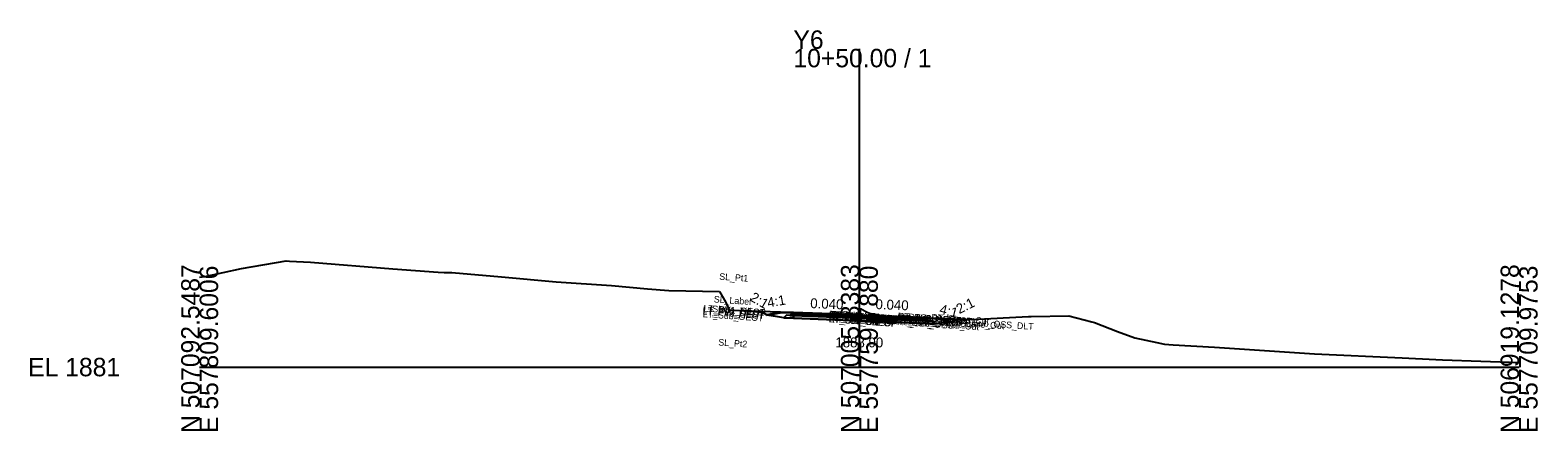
# Model space of a CAD drawing. Extents: x -26 to 203, y -10 to 1539.
# Drawn here: x -25.7 to 202.8, y 490.3 to 551.2 of the extents above; entities that cross this region are included whole.
import ezdxf

# ---------------------------------------------------------------- set-up
doc = ezdxf.new("R2010")
doc.units = 0
for name, color, linetype in [('Default', 7, 'Continuous'), ('Exist Cross Section Cell', 7, 'Continuous'), ('Exist XS Center Line Elevation Label', 7, 'Continuous'), ('Exist XS Ground Line', 7, 'Continuous'), ('Prop CMT Pvmt Course 1', 7, 'Continuous'), ('Prop CMT Pvmt Course 2', 7, 'Continuous'), ('Prop CMT Pvmt Course 3', 7, 'Continuous'), ('Prop CMT Pvmt Surface', 7, 'Continuous'), ('Prop CMT Pvmt Surface Shoulder', 7, 'Continuous'), ('Prop CMT Shld Paved Course 1', 7, 'Continuous'), ('Prop CMT Shld Paved Course 2', 7, 'Continuous'), ('Prop CMT Shld Paved Course 3', 7, 'Continuous'), ('Prop CMT Slope Grass', 7, 'Continuous'), ('Prop CMT Subgrade Earthwork', 7, 'Continuous'), ('Prop XS Earthwork Shape', 7, 'Continuous'), ('Prop XS SE Text', 7, 'Continuous'), ('Prop XS Side Slope Text', 7, 'Continuous'), ('Raster_Level_1', 7, 'Continuous'), ('Typical Text Asphalt at Bridge Approach CELL', 7, 'Continuous')]:
    doc.layers.add(name, color=color, linetype=linetype)

msp = doc.modelspace()

# ---------------------------------------------------------------- linework, layer by layer
at = {"layer": 'Exist Cross Section Cell'}
for p, q in [((100, 500), (100, 548.32)), ((0, 500), (100, 500)), ((100, 500), (200, 500))]:
    msp.add_line(p, q, dxfattribs=at)
at = {"layer": 'Exist XS Ground Line'}
for p, q in [((0.76, 513.74), (6.35, 514.96)), ((6.35, 514.96), (13.12, 516.11)), ((13.12, 516.11), (13.64, 516.08)), ((13.64, 516.08), (16.8, 515.93)), ((16.8, 515.93), (29.3, 514.91)), ((29.3, 514.91), (36.13, 514.4)), ((36.13, 514.4), (37.05, 514.38)), ((37.05, 514.38), (37.88, 514.37)), ((37.88, 514.37), (38.23, 514.36)), ((38.23, 514.36), (45.76, 513.7)), ((0, 513.66), (0.76, 513.74)), ((45.76, 513.7), (54.04, 512.94)), ((54.04, 512.94), (62.43, 512.4)), ((62.43, 512.4), (67.89, 511.87)), ((67.89, 511.87), (71.12, 511.64)), ((71.12, 511.64), (78.82, 511.45)), ((78.82, 511.45), (79.75, 509.78)), ((79.75, 509.78), (80.27, 508.66)), ((80.27, 508.66), (88.06, 508.41)), ((88.06, 508.41), (94.39, 508.12)), ((94.39, 508.12), (95.34, 508.08)), ((95.34, 508.08), (98.2, 507.97)), ((98.2, 507.97), (100, 507.9)), ((100, 507.9), (106.74, 507.64)), ((106.74, 507.64), (108.1, 507.56)), ((108.1, 507.56), (111.33, 507.43)), ((111.33, 507.43), (117.07, 507.2)), ((117.07, 507.2), (125.64, 507.66)), ((125.64, 507.66), (126.04, 507.69)), ((126.04, 507.69), (131.76, 507.79)), ((131.76, 507.79), (135.22, 506.89)), ((135.22, 506.89), (135.62, 506.77)), ((135.62, 506.77), (139.13, 505.39)), ((139.13, 505.39), (141.73, 504.46)), ((141.73, 504.46), (145.08, 503.75)), ((145.08, 503.75), (146.27, 503.5)), ((146.27, 503.5), (147.54, 503.36)), ((147.54, 503.36), (153.82, 503.03)), ((153.82, 503.03), (165.97, 502.2)), ((165.97, 502.2), (168.99, 502.03)), ((168.99, 502.03), (182.26, 501.42)), ((182.26, 501.42), (187.39, 501.16)), ((187.39, 501.16), (188.38, 501.11)), ((188.38, 501.11), (200, 500.69))]:
    msp.add_line(p, q, dxfattribs=at)
at = {"layer": 'Prop CMT Pvmt Course 1'}
for points in [[(90, 508.31), (90, 508.06)], [(100, 507.91), (90, 508.31)], [(90, 508.06), (100, 507.66)], [(100, 507.66), (100, 507.91)], [(100, 507.91), (110, 507.51)], [(100, 507.66), (100, 507.91)], [(110, 507.26), (100, 507.66)], [(110, 507.51), (110, 507.26)]]:
    msp.add_lwpolyline(points, dxfattribs=at)
msp.add_lwpolyline([(100, 507.66), (100, 507.79), (100, 507.79), (100, 507.66)], close=True, dxfattribs=at)
msp.add_lwpolyline([(100, 507.66), (100, 507.79), (100, 507.79), (100, 507.66)], close=True, dxfattribs=at)
at = {"layer": 'Prop CMT Pvmt Course 2'}
for points in [[(90, 508.06), (90, 507.81)], [(100, 507.66), (90, 508.06)], [(90, 507.81), (100, 507.41)], [(100, 507.41), (100, 507.66)], [(100, 507.41), (100, 507.66)], [(100, 507.66), (110, 507.26)], [(110, 507.01), (100, 507.41)], [(110, 507.26), (110, 507.01)]]:
    msp.add_lwpolyline(points, dxfattribs=at)
at = {"layer": 'Prop CMT Pvmt Course 3'}
for points in [[(90, 507.81), (90, 507.43)], [(100, 507.41), (90, 507.81)], [(90, 507.43), (100, 507.03)], [(100, 507.03), (100, 507.41)], [(100, 507.41), (110, 507.01)], [(100, 507.03), (100, 507.41)], [(110, 506.64), (100, 507.03)], [(110, 507.01), (110, 506.64)]]:
    msp.add_lwpolyline(points, dxfattribs=at)
at = {"layer": 'Prop CMT Pvmt Surface'}
for points in [[(100, 507.91), (90, 508.31)], [(100, 507.91), (110, 507.51)]]:
    msp.add_lwpolyline(points, dxfattribs=at)
at = {"layer": 'Prop CMT Pvmt Surface Shoulder'}
for points in [[(90, 508.31), (90, 508.31)], [(110, 507.51), (110, 507.51)]]:
    msp.add_lwpolyline(points, dxfattribs=at)
at = {"layer": 'Prop CMT Shld Paved Course 1'}
for points in [[(90, 508.31), (89.73, 508.07)], [(89.73, 508.07), (90, 508.06)], [(90, 508.31), (90, 508.31)], [(90, 508.06), (90, 508.31)], [(110, 507.51), (110, 507.51)], [(110, 507.51), (110.26, 507.25)], [(110, 507.26), (110, 507.51)], [(110.26, 507.25), (110, 507.26)]]:
    msp.add_lwpolyline(points, dxfattribs=at)
at = {"layer": 'Prop CMT Shld Paved Course 2'}
for points in [[(90, 508.06), (89.73, 508.07), (89.46, 507.84)], [(89.46, 507.84), (90, 507.81)], [(90, 507.81), (90, 508.06)], [(110, 507.26), (110.26, 507.25), (110.51, 507)], [(110, 507.01), (110, 507.26)], [(110.51, 507), (110, 507.01)]]:
    msp.add_lwpolyline(points, dxfattribs=at)
at = {"layer": 'Prop CMT Shld Paved Course 3'}
for points in [[(90, 507.81), (89.46, 507.84), (88.96, 507.86), (88.55, 507.5)], [(88.55, 507.5), (90, 507.43)], [(90, 507.43), (90, 507.81)], [(110, 507.01), (110.51, 507), (111.01, 506.99), (111.39, 506.61)], [(110, 506.64), (110, 507.01)], [(111.39, 506.61), (110, 506.64)]]:
    msp.add_lwpolyline(points, dxfattribs=at)
at = {"layer": 'Prop CMT Slope Grass'}
for points in [[(90, 508.31), (87.99, 508.29), (85.96, 507.92), (84.96, 508.51)], [(110, 507.51), (112, 507.35), (114, 506.85), (114.88, 507.29)]]:
    msp.add_lwpolyline(points, dxfattribs=at)
at = {"layer": 'Prop CMT Subgrade Earthwork'}
for p, q in [((88.55, 507.5), (85.96, 507.92)), ((111.39, 506.61), (114, 506.85))]:
    msp.add_line(p, q, dxfattribs=at)
for points in [[(80.49, 508.65), (80.5, 508.65)], [(90, 507.43), (88.55, 507.5)], [(100, 507.03), (90, 507.43)], [(100, 507.03), (110, 506.64)], [(110, 506.64), (111.39, 506.61)]]:
    msp.add_lwpolyline(points, dxfattribs=at)
at = {"layer": 'Prop XS Earthwork Shape'}
for points in [[(84.88, 508.51), (88.06, 508.41), (94.39, 508.12), (95.34, 508.08), (98.2, 507.97), (100, 507.87), (90, 508.27), (87.99, 508.24), (85.96, 507.88)], [(100, 507.87), (108.1, 507.56), (110, 507.47), (112, 507.31), (114, 506.81), (111.39, 506.56), (110, 506.59), (100, 506.99), (90, 507.39), (88.55, 507.46), (85.96, 507.88), (87.99, 508.24), (90, 508.27)], [(100, 507.87), (106.74, 507.64), (108.1, 507.56)], [(110, 507.47), (111.33, 507.43), (114.96, 507.29), (114, 506.81), (112, 507.31)]]:
    msp.add_lwpolyline(points, close=True, dxfattribs=at)
at = {"layer": 'Raster_Level_1'}
msp.add_line((100, 500), (100, 523.12), dxfattribs=at)

# ---------------------------------------------------------------- texts
at = {"layer": 'Default'}
msp.add_text('-', height=0.0001, dxfattribs=at).set_placement((0, 500))
at = {"layer": 'Exist Cross Section Cell'}
for s, p in [('Y6', (90, 548.32)), ('10+50.00 / 1', (90, 545.52)), ('EL 1881', (-26, 498.6))]:
    msp.add_text(s, height=2.8, dxfattribs=at).set_placement(p)
for s, p in [('N 507092.5487', (0, 490)), ('E 557809.6006', (2.8, 490)), ('N 507005.8383', (100, 490)), ('E 557759.7880', (102.8, 490)), ('N 506919.1278', (200, 490)), ('E 557709.9753', (202.8, 490))]:
    msp.add_text(s, height=2.8, rotation=90, dxfattribs=at).set_placement(p)
at = {"layer": 'Exist XS Center Line Elevation Label'}
msp.add_text('1888.90', height=1.5, dxfattribs=at).set_placement((96.36, 502.99))
at = {"layer": 'Prop XS SE Text'}
for p in [(92.53, 508.96), (102.42, 508.81)]:
    msp.add_text('0.040', height=1.5, rotation=357.7094, dxfattribs=at).set_placement(p)
at = {"layer": 'Prop XS Side Slope Text'}
for s, rotation, p in [('2:1', 329.5485, (83.28, 510.18)), ('4:1', 10.1498, (86.17, 509.02)), ('2:1', 26.5651, (115.14, 508.03)), ('4:1', 345.9638, (112.03, 508.12))]:
    msp.add_text(s, height=1.5, rotation=rotation, dxfattribs=at).set_placement(p)
at = {"layer": 'Typical Text Asphalt at Bridge Approach CELL'}
for s, p in [('SL_Pt1', (78.74, 513.27)), ('SL_Label', (77.91, 509.82)), ('LT_PV2_OEOT', (76.21, 508.19)), ('LT_PV2_OEOT', (76.21, 508.19)), ('LT_PV3_OEOT', (76.21, 507.94)), ('LT_PV3_OEOT', (76.21, 507.94)), ('LT_Sub_OEOT', (76.24, 507.57)), ('LT_Sub_OEOT', (76.24, 507.57)), ('LT_PV1_OEOT', (76.33, 508.44)), ('LT_PV1_OEOT', (76.33, 508.44)), ('LT_PS1_OEOP', (76.37, 508.43)), ('LT_PS1_OEOP', (76.37, 508.43)), ('Slope_Fill', (77.68, 508.35)), ('RT_PV2_OEEOP', (95.31, 507.44)), ('RT_PV3_OEEOP', (95.31, 507.19)), ('RT_Sub_OEEOP', (95.33, 506.82)), ('LT_PV2_OEEOP', (95.37, 507.44)), ('LT_PV3_OEEOP', (95.37, 507.19)), ('LT_Sub_OEEOP', (95.39, 506.81)), ('RT_PV1_OEEOP', (95.43, 507.56)), ('LT_PV1_OEEOP', (95.49, 507.55)), ('RT_PV2_IEEOP', (95.69, 507.42)), ('LT_PV2_IEEOP', (95.75, 507.41)), ('RT_PV1_IEEOP', (95.81, 507.53)), ('LT_PV1_IEEOP', (95.87, 507.53)), ('PV2_PGL', (97.32, 507.3)), ('PV1_PGL', (97.44, 507.54)), ('RT_Sub_Trench_Out', (105.42, 506.48)), ('RT_PS3_Shelf_Out', (105.59, 506.82)), ('RT_PV2_OEOT', (105.66, 507.02)), ('RT_PV3_OEOT', (105.66, 506.77)), ('RT_Sub_OEOT', (105.69, 506.39)), ('RT_PV1_OEOT', (105.78, 507.26)), ('RT_PS1_OEOP', (105.82, 507.26)), ('RT_PS2_OEOP', (105.96, 507.01)), ('RT_PS3_OEOP', (106.21, 506.75)), ('RT_SS_Ditch_Base_Out', (107.18, 506.78)), ('RT_GS_OS_CTL', (107.38, 507.13)), ('RT_Slope_Cut', (110.88, 507.07)), ('RT_Sub_OSS_DLT', (114.66, 506.46)), ('SL_Pt2', (78.59, 503.28))]:
    msp.add_text(s, height=1, rotation=356, dxfattribs=at).set_placement(p)

doc.saveas('drawing.dxf')
